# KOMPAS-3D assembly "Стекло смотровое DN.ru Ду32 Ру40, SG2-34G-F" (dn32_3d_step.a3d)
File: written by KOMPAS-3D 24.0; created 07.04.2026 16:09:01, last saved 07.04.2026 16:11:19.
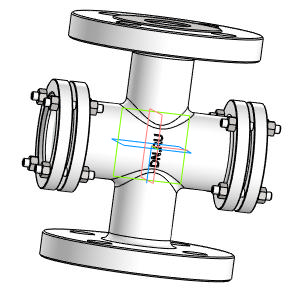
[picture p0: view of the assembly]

Document properties: Автор: Main; Полное имя файла: D:\DN.ru Аутсерс\Стекло смотровое DN.ru\Исходники\Стекло смотровое DN.ru SG2-34G-F тип В ГОСТ 21836-2021 Ду32 Ру40, углеродистая сталь, фланцевое\dn32_3d_step.a3d

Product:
- Component [detail]: Деталь  | qty 1  | pos. 1  | Масса: 5.843223; Автор: Main; additional columns: Типовые; source file: ДетальДеталь.m3d
- Component [detail]: Стекло  | qty 2  | pos. 2  | Масса: 0.08342; Автор: Main; source file: СтеклоСтекло.m3d
- Component [detail]: ANSI B18.2.4.2M - M6x1 - 10  | designation ANSI B18.2.4.2M - M6x1  | qty 16  | pos. 3  | Масса: 0.003008; Комментарий: Типы метрических   шестигранных гаек   2; Автор: Main; additional columns: Сталь, мягкая; source file: ANSI B18.2.4.2M - M6x1ANSI B18.2.4.2M - M6x1 - 10.m3d
- Part/product: Стекло смотровое DN.ru Ду32 Ру40  | designation SG2-34G-F
    Масса: 6.2
    Раздел спецификации: Прочие изделия
    Примечание: D500-00082

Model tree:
1. Массив по концентрической сетке:1  (labels: Грань.Твердое тело1; Ребро.Твердое тело1; Ребро.Solid1; Грань.Solid1)  (4 pattern instances)
     Шаг 2 = 360

Expressions: SG2-34G-F
Referenced files in D:\DN.ru Аутсерс\Стекло смотровое DN.ru\Исходники\Стекло смотровое DN.ru SG2-34G-F тип В ГОСТ 21836-2021 Ду32 Ру40, углеродистая сталь, фланцевое\: ДетальДеталь.m3d, СтеклоСтекло.m3d, ANSI B18.2.4.2M - M6x1ANSI B18.2.4.2M - M6x1 - 10.m3d
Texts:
  Стекло Стекло (1)
  Стекло Стекло (2)
  ANSI B18.2.4.2M - M6x1 ANSI B18.2.4.2M - M6x1 - 10 (1)
  ANSI B18.2.4.2M - M6x1 ANSI B18.2.4.2M - M6x1 - 10 (2)
  ANSI B18.2.4.2M - M6x1 ANSI B18.2.4.2M - M6x1 - 10 (3)
  ANSI B18.2.4.2M - M6x1 ANSI B18.2.4.2M - M6x1 - 10 (4)
  ANSI B18.2.4.2M - M6x1 ANSI B18.2.4.2M - M6x1 - 10 (5)
  ANSI B18.2.4.2M - M6x1 ANSI B18.2.4.2M - M6x1 - 10 (6)
  ANSI B18.2.4.2M - M6x1 ANSI B18.2.4.2M - M6x1 - 10 (7)
  ANSI B18.2.4.2M - M6x1 ANSI B18.2.4.2M - M6x1 - 10 (8)
  ANSI B18.2.4.2M - M6x1 ANSI B18.2.4.2M - M6x1 - 10 (9)
  ANSI B18.2.4.2M - M6x1 ANSI B18.2.4.2M - M6x1 - 10 (10)
  ANSI B18.2.4.2M - M6x1 ANSI B18.2.4.2M - M6x1 - 10 (11)
  ANSI B18.2.4.2M - M6x1 ANSI B18.2.4.2M - M6x1 - 10 (12)
  ANSI B18.2.4.2M - M6x1 ANSI B18.2.4.2M - M6x1 - 10 (13)
  ANSI B18.2.4.2M - M6x1 ANSI B18.2.4.2M - M6x1 - 10 (14)
  ANSI B18.2.4.2M - M6x1 ANSI B18.2.4.2M - M6x1 - 10 (15)
  ANSI B18.2.4.2M - M6x1 ANSI B18.2.4.2M - M6x1 - 10 (16)
  Ось Z.Начало координат
  Ось X.Начало координат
